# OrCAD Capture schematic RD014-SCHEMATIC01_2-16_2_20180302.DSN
size A3
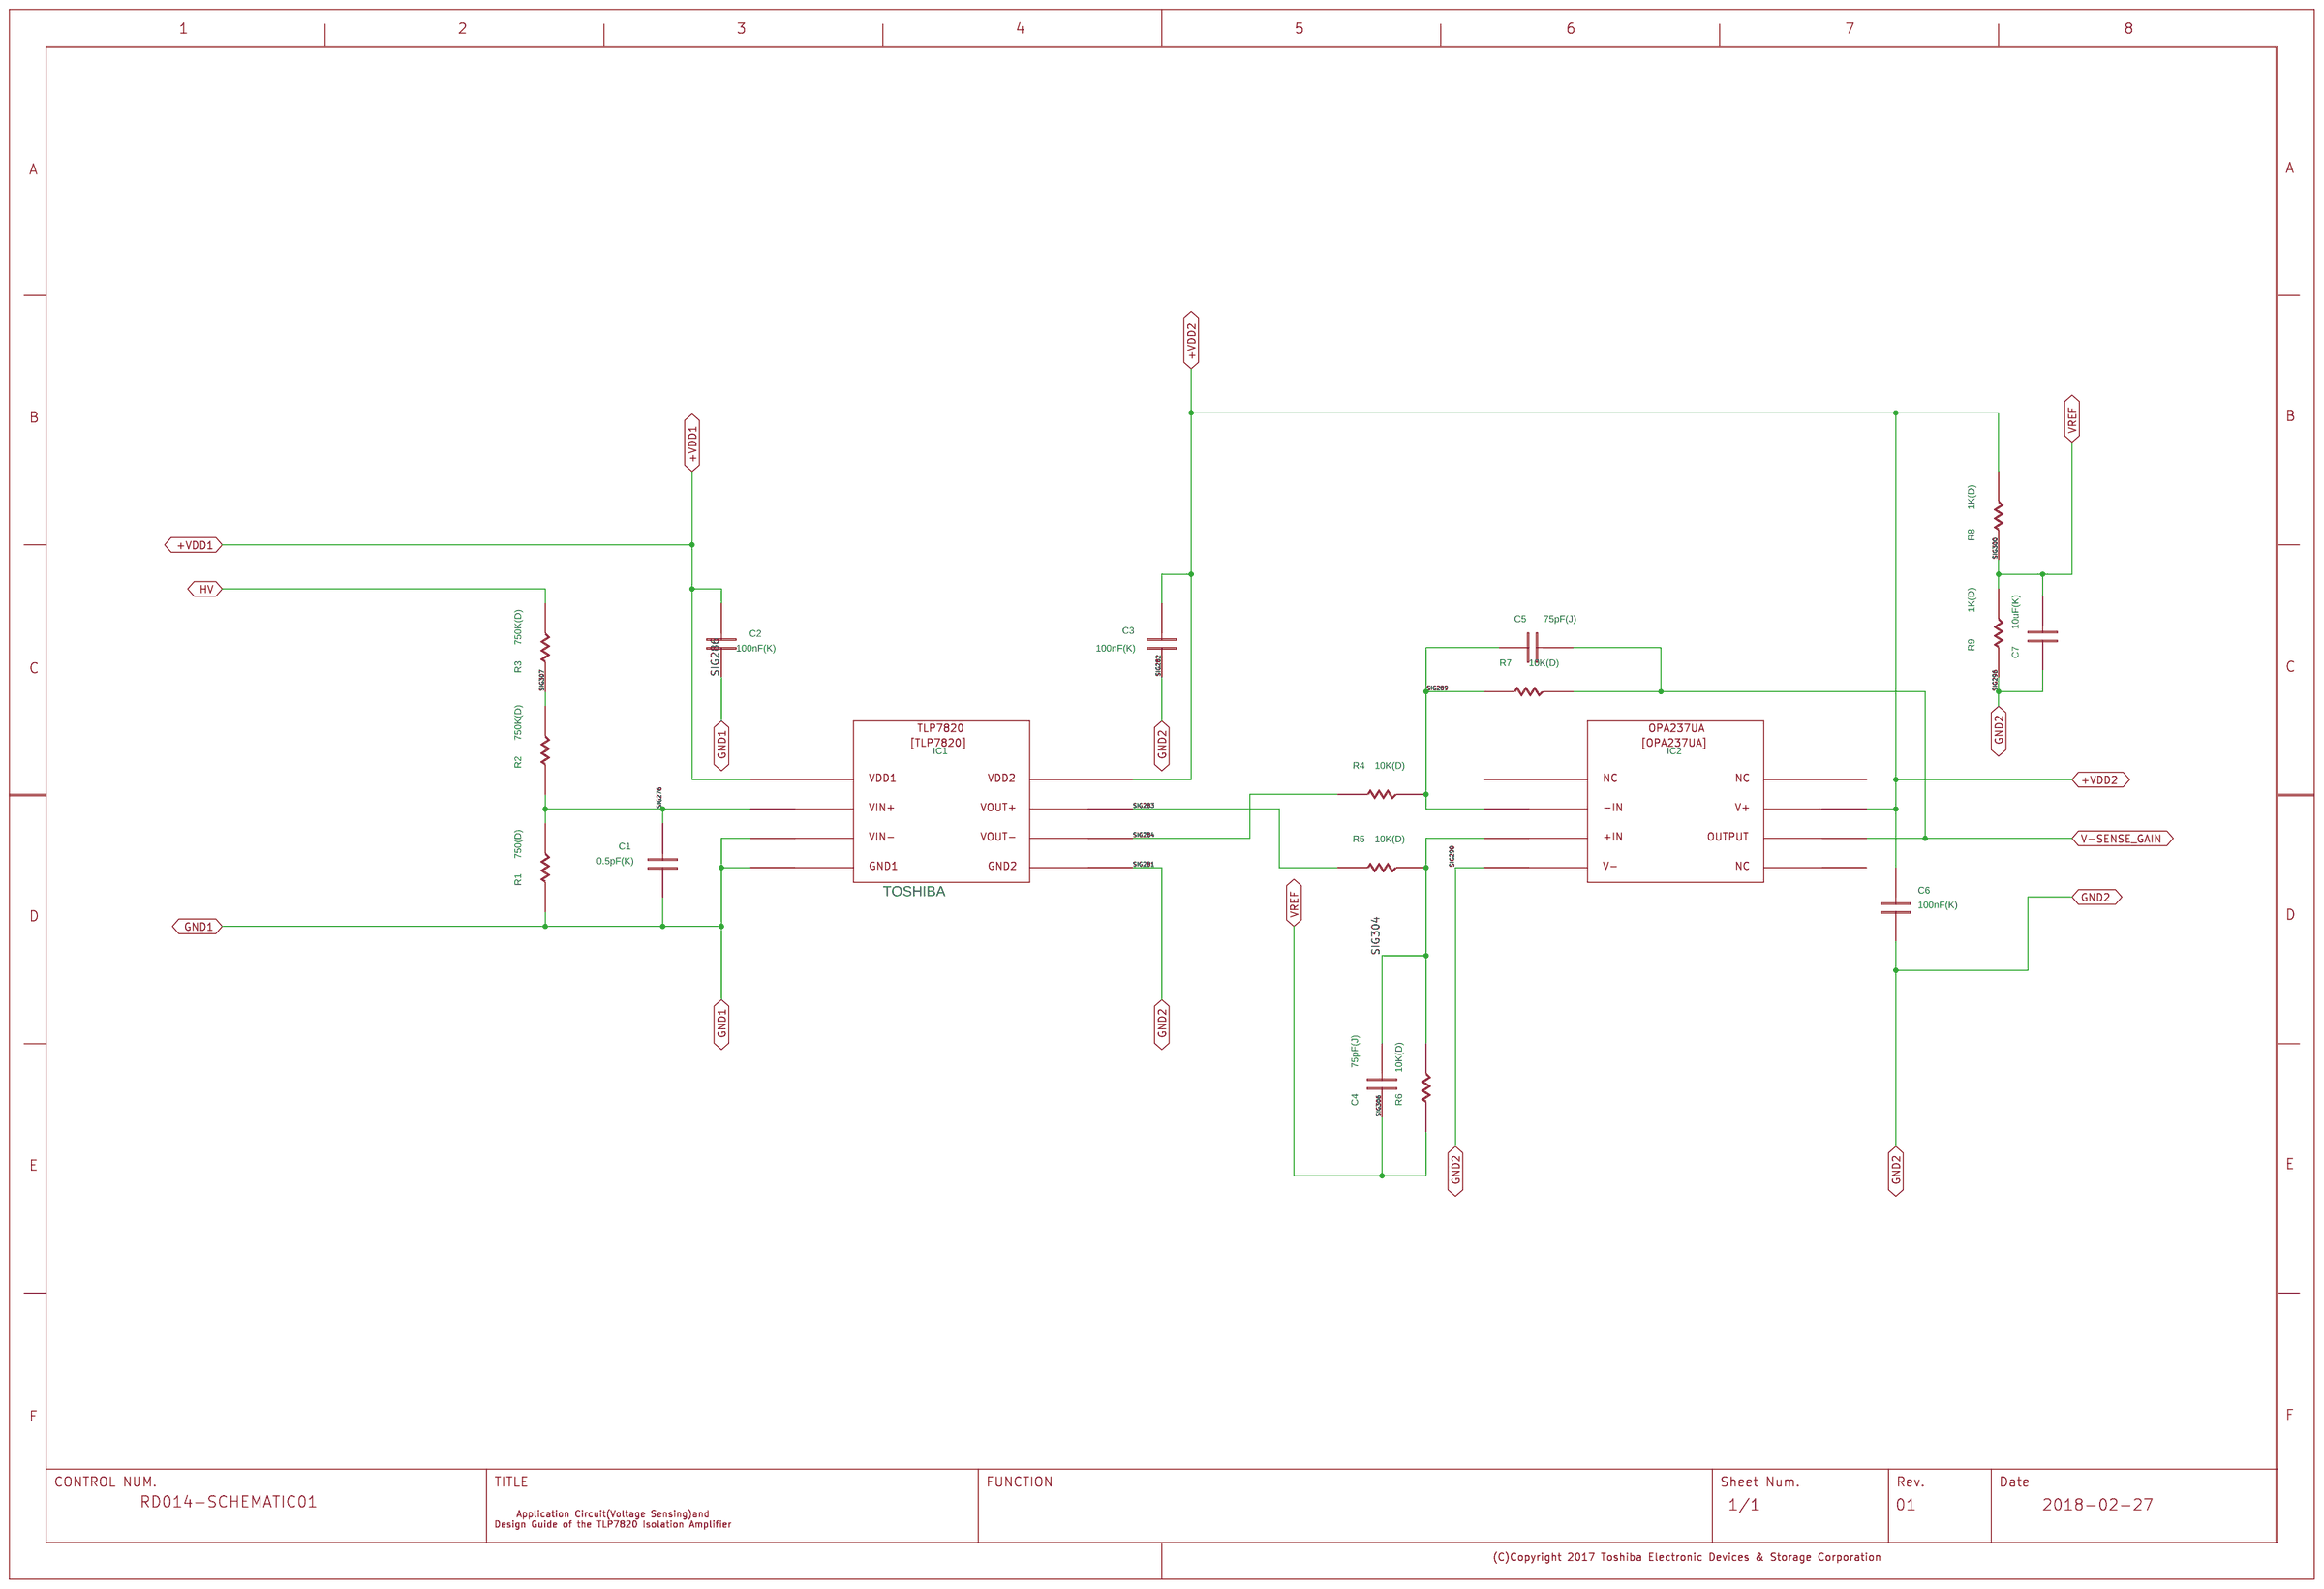
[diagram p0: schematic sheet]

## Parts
C1  C
C2  C
C3  C
C4  C
C5  C
C6  C
C7  C
IC1  S-TLP7820
IC2  S-OPA237UA
R1  R
R2  R
R3  R
R4  R
R5  R
R6  R
R7  R
R8  R
R9  R
U?#1  WAKU_DEF100

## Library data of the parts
C1 = C: COMP: PRT_7; COMPONENTTYPE: 4; GCOUNT: 1; MAXGCOUNT: 1; SIZECODESMD: 1005; VAL1: 0.5pF(K); VAL2: 50V
C2 C3 C6 = C: COMP: PRT_8; COMPONENTTYPE: 4; GCOUNT: 1; MAXGCOUNT: 1; SIZECODESMD: 2012; VAL1: 100nF(K); VAL2: 25V
C4 C5 = C: COMP: PRT_9; COMPONENTTYPE: 4; GCOUNT: 1; MAXGCOUNT: 1; SIZECODESMD: 1608; VAL1: 75pF(J); VAL2: 100V
C7 = C: COMP: PRT_10; COMPONENTTYPE: 4; GCOUNT: 1; MAXGCOUNT: 1; SIZECODESMD: 2012; VAL1: 10uF(K); VAL2: 16V
IC1 = S-TLP7820: COMP: PRT_1; COMPONENTTYPE: 4; USERCOMPTEXT3: TOSHIBA
IC2 = S-OPA237UA: COMP: PRT_2; COMPONENTTYPE: 4; USERCOMPTEXT3: Texas Instruments
R1 = R: COMP: PRT_3; COMPONENTTYPE: 4; GCOUNT: 1; MAXGCOUNT: 1; OLDCOMPONENTID: 243; SIZECODESMD: 2012; VAL1: 750(D); VAL2: 250mW
R2 R3 = R: COMP: PRT_4; COMPONENTTYPE: 4; GCOUNT: 1; MAXGCOUNT: 1; SIZECODESMD: 6332; VAL1: 750K(D); VAL2: 1W
R4-R7 = R: COMP: PRT_5; COMPONENTTYPE: 4; GCOUNT: 1; MAXGCOUNT: 1; SIZECODESMD: 2012; VAL1: 10K(D); VAL2: 250mW
R8 R9 = R: COMP: PRT_6; COMPONENTTYPE: 4; GCOUNT: 1; MAXGCOUNT: 1; SIZECODESMD: 2012; VAL1: 1K(D); VAL2: 250mW
U?#1 = WAKU_DEF100: COMPONENTTYPE: 2; DATE: 2018-02-27; DRAWINGNUMBER: RD014-SCHEMATIC01; FUNCTION: POWER block; REVISION: 01; SHEETNUMBER: 1/1; TITLE: Application Circuit(Voltage Sensing)and / Design Guide of the TLP7820 Isolation Amplifier; UPDATEDATE: 2018/03/02; UPDATETIME: 19:49:31; UPDATEUSER: f1043010

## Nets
+VDD1: C2.2 IC1.1
+VDD2: C3.2 C6.2 IC1.8 IC2.7 R8.2
GND1: C1.1 C2.1 IC1.3 IC1.4 R1.1
GND2: C3.1 C6.1 C7.1 IC1.5 IC2.4 R9.1
HV: R3.2
SIG276: C1.2 IC1.2 R1.2 R2.1
SIG283: IC1.7 R5.1
SIG284: IC1.6 R4.1
SIG289: C5.1 IC2.2 R4.2 R7.1
SIG304: C4.2 IC2.3 R5.2 R6.2
SIG307: R2.2 R3.1
V-SENSE_GAIN: C5.2 IC2.6 R7.2
VREF: C4.1 C7.2 R6.1 R8.1 R9.2

Not connected (* = marked no-connect by the designer): IC2 1 5 8
